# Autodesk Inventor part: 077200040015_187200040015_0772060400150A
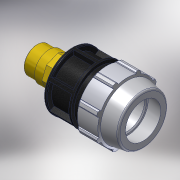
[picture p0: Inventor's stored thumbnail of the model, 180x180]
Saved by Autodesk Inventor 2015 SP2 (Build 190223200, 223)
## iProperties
Created: 2017-02
Part Number: 077200040015_187200040015_0772060400150A
Material: PVC-Piping
Description: PLASSON MALE ADAPTOR INTEGRAL BRASS THREAD 40-1.1/2"
Document SubType Name: Modeling
Designer: KIM
Mass: 92.6774 g
Surface Area: 199.44 cm^2
Volume: 66.1981 cm^3
Density: 1.4 g/cm^3
Appearance: PTFE
Author: KIM
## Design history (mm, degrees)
derived "07720.ipt"
feature "Solid1::07720.ipt"
tag "TaggingFeature1"
body "Solid1"
other parameters: "d4" = 21.85714, "d5" = 21.85714, "d7" = 82, "d8" = 61.5, "d9" = 21.85714, "d11" = 4.37143, "d12" = 65.6, "d13" = 120 deg, "d15" = 10 deg, "d16" = 73.8, "d18" = 2, "d19" = 35 deg, "d20" = 17.5 deg, "d21" = 76.26, "d23" = 0, "d25" = 360 deg, "d27" = 1.64, "d34" = 4.1, "d36" = 0, "d42" = 30.6, "d43" = 2.46, "d46" = 1.2, "d49" = 91, "d51" = 153, "d53" = 0.8, "d55" = 360 deg, "d59" = 30.6, "d60" = 47.803, "d61" = 52.5833, "d62" = 22, "d63" = 51, "d64" = 33.4621, "d65" = 153, "d66" = 15.74406, "d67" = 0, "d68" = 0.8, "d71" = 30 deg, "d72" = 43.0227, "E_" = 82, "H_" = 153, "l_" = 91, "l_2" = 22, "R_" = 47.803, "d73" = 26.24009
